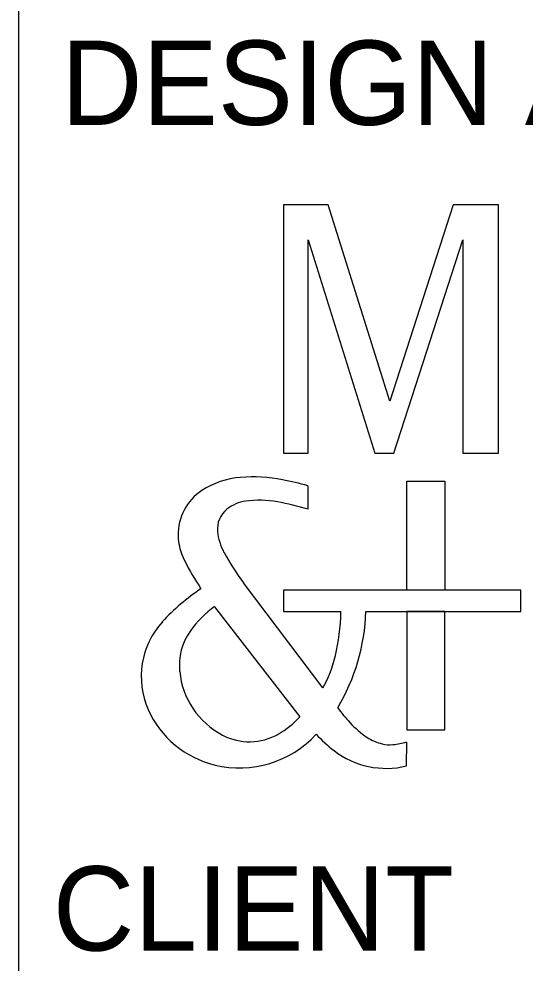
# Model space of a CAD drawing. Extents: x -598712 to 598841, y -1929203 to 1929250.
# Drawn here: x 32 to 32.6, y 3.356 to 4.476 of the extents above; entities that cross this region are included whole.
import ezdxf

# ---------------------------------------------------------------- set-up
doc = ezdxf.new("R2010")
doc.units = 0
for name, color, linetype in [('PM_P_Stop_Line', 7, 'Continuous'), ('SG_P_Controllers', 7, 'Continuous'), ('SG_P_Heads', 7, 'Continuous')]:
    doc.layers.add(name, color=color, linetype=linetype)

msp = doc.modelspace()

# ---------------------------------------------------------------- linework, layer by layer
at = {"layer": 'PM_P_Stop_Line'}
for p, q in [((32.3427, 3.8941), (32.3427, 3.9218)), ((32.4598, 3.7982), (32.4599, 3.9273)), ((32.4599, 3.9273), (32.5048, 3.9273)), ((32.5048, 3.9273), (32.5048, 3.7982)), ((32.3602, 3.6822), (32.2664, 3.807)), ((32.2318, 3.7786), (32.333, 3.648)), ((32.4598, 3.7727), (32.4597, 3.6326)), ((32.5048, 3.7727), (32.4598, 3.7727)), ((32.5047, 3.6326), (32.5048, 3.7727)), ((32.1699, 3.7605), (32.1701, 3.7608)), ((32.4597, 3.6326), (32.5047, 3.6326)), ((32.4596, 3.5897), (32.4597, 3.6181))]:
    msp.add_line(p, q, dxfattribs=at)
msp.add_lwpolyline([(32.3427, 3.9606), (32.3428, 4.2138), (32.4219, 3.9606), (32.4444, 3.9606), (32.5262, 4.2138), (32.5261, 3.9606), (32.5685, 3.9606), (32.5686, 4.2552), (32.5148, 4.2552), (32.4396, 4.0225), (32.3667, 4.2553), (32.3136, 4.2553), (32.3135, 3.9607)], close=True, dxfattribs=at)
msp.add_lwpolyline([(32.3427, 3.9606), (32.3428, 4.2138), (32.4219, 3.9606), (32.4444, 3.9606), (32.5262, 4.2138), (32.5261, 3.9606), (32.5685, 3.9606), (32.5686, 4.2552), (32.5148, 4.2552), (32.4396, 4.0225), (32.3667, 4.2553), (32.3136, 4.2553), (32.3135, 3.9607)], close=True, dxfattribs=at)
msp.add_lwpolyline([(32.4113, 3.7727), (32.595, 3.7727), (32.595, 3.7982), (32.3135, 3.7982), (32.3135, 3.7728), (32.3818, 3.7727)], dxfattribs=at)
for centre, radius, start, end in [((32.2704, 3.8341), 0.0981, 94.5206, 123.1061), ((32.2773, 3.7474), 0.1851, 79.0563, 94.5206), ((32.2447, 3.579), 0.3566, 74.0516, 79.0563), ((32.2507, 3.8643), 0.062, 123.1061, 181.2152), ((32.2757, 3.8572), 0.0471, 98.3723, 128.329), ((32.2853, 3.7917), 0.1132, 79.2666, 98.3723), ((32.2397, 3.5511), 0.3581, 73.2803, 79.2666), ((32.2648, 3.871), 0.0295, 128.329, 186.0821), ((32.3016, 3.8749), 0.0666, 186.0821, 208.5769), ((32.2571, 3.8645), 0.0684, 181.2152, 207.1091), ((32.5018, 3.9839), 0.2945, 208.5769, 216.933), ((32.5072, 3.9925), 0.3493, 207.1091, 213.4656), ((32.353, 3.5934), 0.2479, 123.6, 137.6035), ((32.301, 3.6813), 0.1194, 125.3927, 144.9042), ((32.1732, 3.7805), 0.2382, 329.2356, 358.1314), ((32.2414, 3.6957), 0.0964, 137.6035, 203.9313), ((32.2619, 3.7087), 0.0717, 144.9042, 185.7554), ((32.2861, 3.7112), 0.096, 185.7554, 242.1528), ((32.2592, 3.7037), 0.116, 203.9313, 256.6813), ((32.573, 3.8053), 0.2441, 216.933, 222.2898), ((32.2535, 3.7212), 0.1081, 299.979, 317.3992), ((32.4725, 3.7139), 0.1082, 222.2898, 236.5762), ((32.2612, 3.712), 0.1246, 256.6813, 317.1089), ((32.2733, 3.6869), 0.0685, 242.1528, 299.979), ((32.4772, 3.7423), 0.1697, 222.685, 232.3525), ((32.4432, 3.6696), 0.0551, 236.5762, 256.9728), ((32.4361, 3.6978), 0.0831, 275.0638, 286.4619), ((32.4355, 3.6882), 0.1014, 232.3525, 283.7629), ((32.4399, 3.6553), 0.0405, 256.9728, 275.0638)]:
    msp.add_arc(centre, radius, start, end, dxfattribs=at)
msp.add_ellipse((32.3411, 3.7739), major_axis=(-0.0031, -0.1077), ratio=0.377453, start_param=0.562501, end_param=1.570796, dxfattribs=at)
at = {"layer": 'SG_P_Heads'}
msp.add_line((32, 0.5), (32, 21.5), dxfattribs=at)

# ---------------------------------------------------------------- texts
at = {"layer": 'PM_P_Stop_Line'}
msp.add_text('DESIGN AGENCY', height=0.1, dxfattribs=at).set_placement((32.05, 4.35))
at = {"layer": 'SG_P_Controllers'}
msp.add_text('CLIENT', height=0.1, dxfattribs=at).set_placement((32.0402, 3.3707))

doc.saveas('drawing.dxf')
